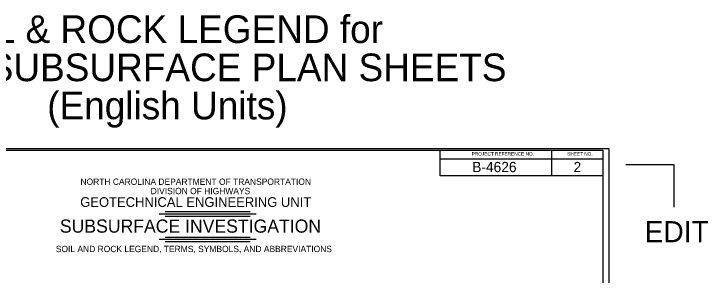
# Model space of a CAD drawing. Extents: x 278618 to 280654, y 171155 to 171855.
# Drawn here: x 280512.3 to 280644.2, y 171622.8 to 171672.4 of the extents above; entities that cross this region are included whole.
import ezdxf

# ---------------------------------------------------------------- set-up
doc = ezdxf.new("R2010")
doc.units = 0
for name, color, linetype in [('Geotech Sheets and Borders Cell', 7, 'Continuous'), ('Scratch_Level_0', 7, 'Continuous'), ('Scratch_Level_2', 7, 'Continuous'), ('Scratch_Level_4', 7, 'Continuous'), ('Sheet Plot Border Inside CELL', 7, 'Continuous')]:
    doc.layers.add(name, color=color, linetype=linetype)

msp = doc.modelspace()

# ---------------------------------------------------------------- linework, layer by layer
at = {"layer": 'Geotech Sheets and Borders Cell'}
for p, q in [((280614.4, 171646.49), (280614.4, 171641.61)), ((280593.27, 171644.86), (280624.15, 171644.86)), ((280539.93, 171634.41), (280558.37, 171634.41)), ((280541.06, 171634.84), (280557.24, 171634.84)), ((280541.06, 171633.98), (280557.24, 171633.98)), ((280539.93, 171629.58), (280558.37, 171629.58)), ((280541.06, 171630.01), (280557.24, 171630.01)), ((280541.06, 171629.15), (280557.24, 171629.15))]:
    msp.add_line(p, q, dxfattribs=at)
for points in [[(280474.15, 171646.49), (280624.15, 171646.49), (280624.15, 171541.49), (280474.15, 171541.49)], [(280593.27, 171646.49), (280624.15, 171646.49), (280624.15, 171641.61), (280593.27, 171641.61)]]:
    msp.add_lwpolyline(points, close=True, dxfattribs=at)
at = {"layer": 'Scratch_Level_0'}
msp.add_line((280625.4, 171646.77), (280625.4, 171646.77), dxfattribs=at)
at = {"layer": 'Scratch_Level_4'}
msp.add_lwpolyline([(280637.74, 171635.71), (280637.74, 171643.73), (280628.53, 171643.73)], dxfattribs=at)
at = {"layer": 'Sheet Plot Border Inside CELL'}
msp.add_lwpolyline([(280458.63, 171541.2), (280625.4, 171541.2), (280625.4, 171646.77), (280458.63, 171646.77)], close=True, dxfattribs=at)

# ---------------------------------------------------------------- texts
at = {"layer": 'Geotech Sheets and Borders Cell'}
for s, height, p in [('PROJECT REFERENCE NO.', 0.65, (280599.27, 171645.48)), ('SHEET NO.', 0.65, (280617.41, 171645.48)), ('B-4626', 1.95, (280599.38, 171642.33)), ('2', 1.95, (280618.61, 171642.33)), ('NORTH CAROLINA DEPARTMENT OF TRANSPORTATION', 1.2, (280524.99, 171639.92)), ('DIVISION OF HIGHWAYS', 1.2, (280538.32, 171638.15)), ('GEOTECHNICAL ENGINEERING UNIT', 1.845, (280524.94, 171635.73)), ('SUBSURFACE INVESTIGATION', 2.5, (280521.08, 171630.84)), ('SOIL AND ROCK LEGEND, TERMS, SYMBOLS, AND ABBREVIATIONS', 1.2, (280520.31, 171627.15))]:
    msp.add_text(s, height=height, dxfattribs=at).set_placement(p)
at = {"layer": 'Scratch_Level_2'}
for s, p in [('SOIL & ROCK LEGEND for', (280496.61, 171666.85)), ('11 x 17 SUBSURFACE PLAN SHEETS', (280482.59, 171659.6)), ('(English Units)', (280518.68, 171652.35))]:
    msp.add_text(s, height=5.25, dxfattribs=at).set_placement(p)
at = {"layer": 'Scratch_Level_4'}
msp.add_text('EDIT', height=4, dxfattribs=at).set_placement((280632.1, 171629.03))

doc.saveas('drawing.dxf')
